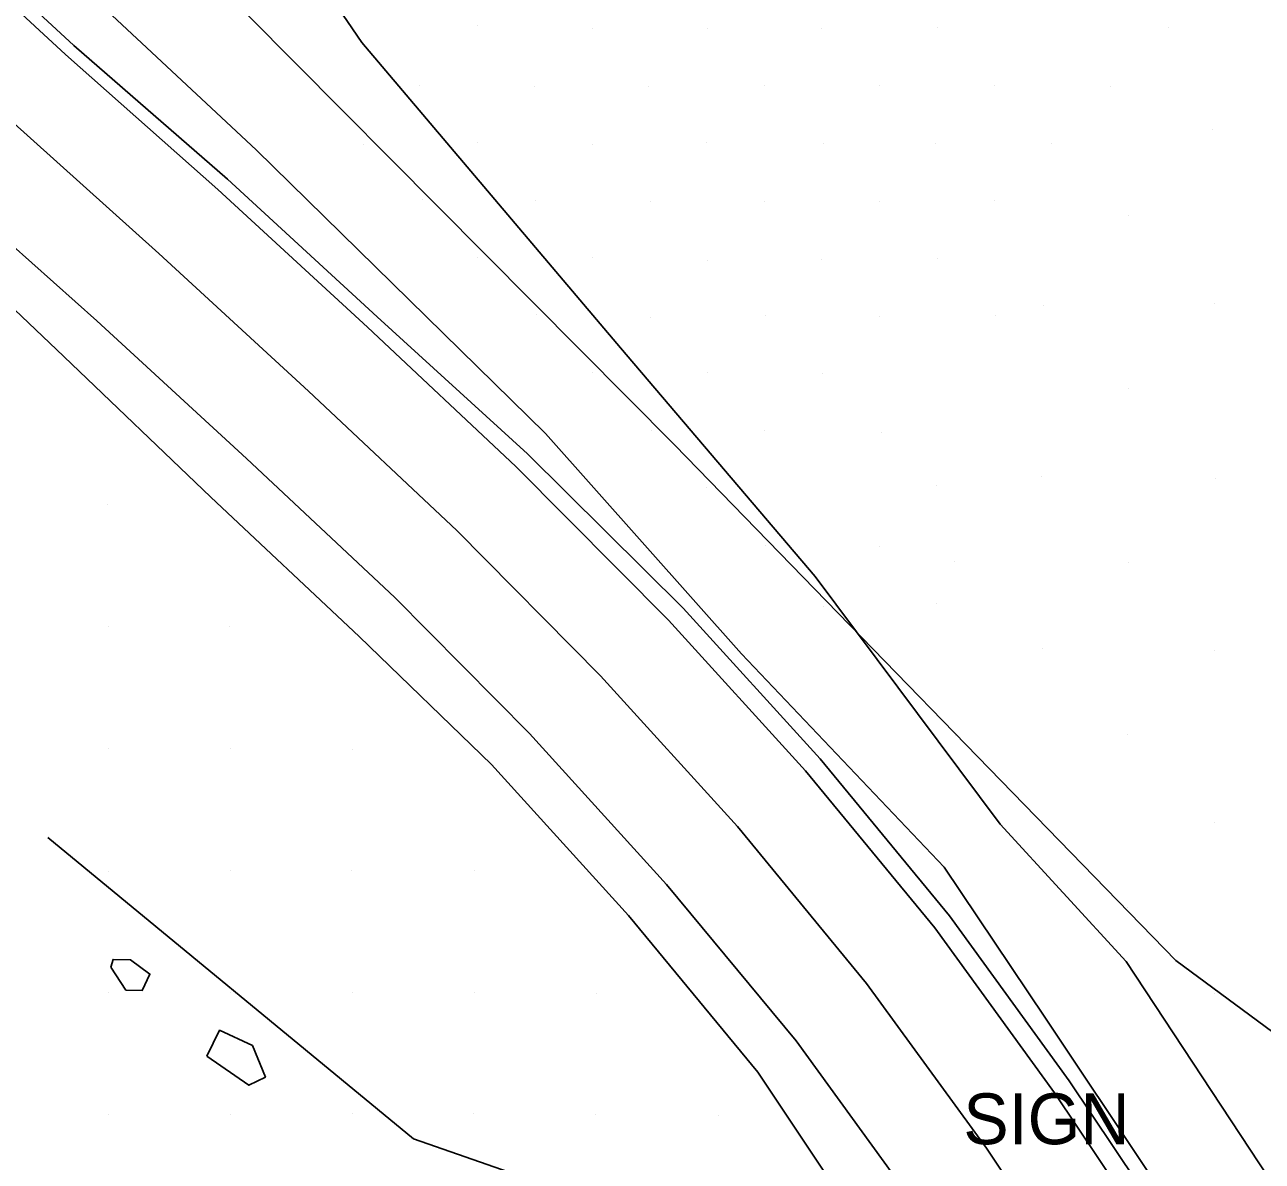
# Model space of a CAD drawing. Extents: x 1602514 to 1609837, y 863887 to 871157.
# Drawn here: x 1605243.4 to 1605395.4, y 866343.2 to 866482.9 of the extents above; entities that cross this region are included whole.
import ezdxf

# ---------------------------------------------------------------- set-up
doc = ezdxf.new("R2010")
doc.units = 0
for name, color, linetype in [('Roadway-Signs', 7, 'Continuous'), ('Survey-Centerline', 7, 'Continuous'), ('Survey-Edge of pavement', 7, 'Continuous'), ('Survey-Ridge Lines', 7, 'Continuous'), ('Survey-Shoulders', 7, 'Continuous'), ('Survey-Spot dirt', 7, 'Continuous'), ('Survey-Vegetation trees', 7, 'Continuous'), ('USER-Boulder', 7, 'Continuous')]:
    doc.layers.add(name, color=color, linetype=linetype)

msp = doc.modelspace()

# ---------------------------------------------------------------- linework, layer by layer
at = {"layer": 'Survey-Centerline'}
msp.add_lwpolyline([(1605037.69, 866656.39), (1605055.94, 866639.3), (1605074.48, 866622.54), (1605093.22, 866605.99), (1605111.81, 866589.27), (1605130.38, 866572.54), (1605149.03, 866555.9), (1605167.54, 866539.1), (1605186.09, 866522.35), (1605204.45, 866505.38), (1605222.87, 866488.48), (1605241.24, 866471.52), (1605259.83, 866454.8), (1605278.24, 866437.88), (1605296.47, 866420.77), (1605314.1, 866402.9), (1605330.94, 866384.38), (1605346.83, 866365.09), (1605361.55, 866344.83), (1605375.5, 866323.96)], dxfattribs=at)
msp.add_lwpolyline([(1605037.69, 866656.39), (1605055.94, 866639.3), (1605074.48, 866622.54), (1605093.22, 866605.99), (1605111.81, 866589.27), (1605130.38, 866572.54), (1605149.03, 866555.9), (1605167.54, 866539.1), (1605186.09, 866522.35), (1605204.45, 866505.38), (1605222.87, 866488.48), (1605241.24, 866471.52), (1605259.83, 866454.8), (1605278.24, 866437.88), (1605296.47, 866420.77), (1605314.1, 866402.9), (1605330.94, 866384.38), (1605346.83, 866365.09), (1605361.55, 866344.83), (1605375.5, 866323.96)], dxfattribs=at)
at = {"layer": 'Survey-Edge of pavement'}
for points in [[(1605045, 866665.21), (1605063.24, 866647.41), (1605081.79, 866630.65), (1605100.27, 866613.81), (1605118.67, 866596.89), (1605137.24, 866580.16), (1605155.84, 866563.45), (1605174.61, 866546.94), (1605193.13, 866529.98), (1605211.59, 866513.11), (1605230.01, 866496.21), (1605248.38, 866479.26), (1605267.08, 866462.66), (1605285.49, 866445.74), (1605303.72, 866428.63), (1605322.49, 866409.74), (1605339.33, 866391.21), (1605355.22, 866371.92), (1605369.93, 866351.67), (1605383.89, 866330.79)], [(1605045, 866665.21), (1605063.24, 866647.41), (1605081.79, 866630.65), (1605100.27, 866613.81), (1605118.67, 866596.89), (1605137.24, 866580.16), (1605155.84, 866563.45), (1605174.61, 866546.94), (1605193.13, 866529.98), (1605211.59, 866513.11), (1605230.01, 866496.21), (1605248.38, 866479.26), (1605267.08, 866462.66), (1605285.49, 866445.74), (1605303.72, 866428.63), (1605322.49, 866409.74), (1605339.33, 866391.21), (1605355.22, 866371.92), (1605369.93, 866351.67), (1605383.89, 866330.79)], [(1605024.15, 866652.85), (1605048.37, 866630.9), (1605067.06, 866614.3), (1605085.84, 866597.8), (1605104.37, 866581.02), (1605122.94, 866564.29), (1605141.59, 866547.64), (1605160.11, 866530.85), (1605178.38, 866513.98), (1605196.73, 866497.01), (1605215.15, 866480.11), (1605233.53, 866463.16), (1605252.21, 866446.54), (1605270.61, 866429.62), (1605288.84, 866412.51), (1605305.39, 866395.8), (1605322.22, 866377.27), (1605338.18, 866358.03), (1605352.89, 866337.77)], [(1605024.15, 866652.85), (1605048.37, 866630.9), (1605067.06, 866614.3), (1605085.84, 866597.8), (1605104.37, 866581.02), (1605122.94, 866564.29), (1605141.59, 866547.64), (1605160.11, 866530.85), (1605178.38, 866513.98), (1605196.73, 866497.01), (1605215.15, 866480.11), (1605233.53, 866463.16), (1605252.21, 866446.54), (1605270.61, 866429.62), (1605288.84, 866412.51), (1605305.39, 866395.8), (1605322.22, 866377.27), (1605338.18, 866358.03), (1605352.89, 866337.77)]]:
    msp.add_lwpolyline(points, dxfattribs=at)
at = {"layer": 'Survey-Ridge Lines'}
for points in [[(1605195.3, 866608.5), (1605255.31, 866523.97), (1605284.77, 866480.71), (1605316.58, 866443.2), (1605340.52, 866415.11), (1605363.23, 866384.67), (1605378.71, 866367.8), (1605403.27, 866330.55), (1605412.95, 866304.44), (1605430.55, 866268.66), (1605443.77, 866231.64), (1605454.66, 866201.21), (1605464.16, 866184.87), (1605467.92, 866182.17), (1605470.83, 866178.24), (1605475.29, 866169.59)], [(1605195.3, 866608.5), (1605255.31, 866523.97), (1605284.77, 866480.71), (1605316.58, 866443.2), (1605340.52, 866415.11), (1605363.23, 866384.67), (1605378.71, 866367.8), (1605403.27, 866330.55), (1605412.95, 866304.44), (1605430.55, 866268.66), (1605443.77, 866231.64), (1605454.66, 866201.21), (1605464.16, 866184.87), (1605467.92, 866182.17), (1605470.83, 866178.24), (1605475.29, 866169.59)], [(1605126.79, 866598.12), (1605151.68, 866575.67), (1605188.15, 866541.7), (1605235.1, 866501.78), (1605271.81, 866467.54), (1605307.34, 866432.68), (1605331.43, 866405.59), (1605356.35, 866379.4), (1605368.71, 866360.96), (1605381.73, 866341.47), (1605393.4, 866324.71), (1605405.98, 866300.67), (1605423.07, 866265.61), (1605436.8, 866229.87), (1605447.04, 866198.89), (1605457.58, 866178.46), (1605461.17, 866174.26), (1605463.72, 866171.59), (1605472.78, 866165.22)], [(1605126.79, 866598.12), (1605151.68, 866575.67), (1605188.15, 866541.7), (1605235.1, 866501.78), (1605271.81, 866467.54), (1605307.34, 866432.68), (1605331.43, 866405.59), (1605356.35, 866379.4), (1605368.71, 866360.96), (1605381.73, 866341.47), (1605393.4, 866324.71), (1605405.98, 866300.67), (1605423.07, 866265.61), (1605436.8, 866229.87), (1605447.04, 866198.89), (1605457.58, 866178.46), (1605461.17, 866174.26), (1605463.72, 866171.59), (1605472.78, 866165.22)]]:
    msp.add_lwpolyline(points, dxfattribs=at)
at = {"layer": 'Survey-Shoulders'}
for points in [[(1605020.8, 866649.24), (1605044.41, 866626.5), (1605062.62, 866609.38), (1605081.95, 866593.48), (1605100.89, 866577.16), (1605119.46, 866560.43), (1605138.12, 866543.79), (1605156.63, 866526.99), (1605174.63, 866509.92), (1605193.24, 866493.23), (1605211.66, 866476.33), (1605230.03, 866459.38), (1605248.15, 866442.14), (1605266.22, 866424.86), (1605284.45, 866407.75), (1605300.72, 866391.99), (1605317.55, 866373.46), (1605333.45, 866354.17), (1605347.38, 866333.28)], [(1605020.8, 866649.24), (1605044.41, 866626.5), (1605062.62, 866609.38), (1605081.95, 866593.48), (1605100.89, 866577.16), (1605119.46, 866560.43), (1605138.12, 866543.79), (1605156.63, 866526.99), (1605174.63, 866509.92), (1605193.24, 866493.23), (1605211.66, 866476.33), (1605230.03, 866459.38), (1605248.15, 866442.14), (1605266.22, 866424.86), (1605284.45, 866407.75), (1605300.72, 866391.99), (1605317.55, 866373.46), (1605333.45, 866354.17), (1605347.38, 866333.28)], [(1605118.67, 866596.89), (1605124.9, 866593.16), (1605138.16, 866581.18), (1605157.01, 866564.75), (1605175.69, 866548.14), (1605194.25, 866531.19), (1605212.61, 866514.22), (1605231.03, 866497.32), (1605249.4, 866480.36), (1605268.26, 866463.93), (1605286.67, 866447.02), (1605305.13, 866430.16), (1605324.29, 866411.21), (1605341.12, 866392.68), (1605357.02, 866373.39), (1605371.73, 866353.13), (1605385.69, 866332.26), (1605399.6, 866308.3), (1605412.28, 866286.71), (1605423.44, 866262.16), (1605432.42, 866238.83), (1605440.02, 866215.01), (1605447.78, 866189)], [(1605118.67, 866596.89), (1605124.9, 866593.16), (1605138.16, 866581.18), (1605157.01, 866564.75), (1605175.69, 866548.14), (1605194.25, 866531.19), (1605212.61, 866514.22), (1605231.03, 866497.32), (1605249.4, 866480.36), (1605268.26, 866463.93), (1605286.67, 866447.02), (1605305.13, 866430.16), (1605324.29, 866411.21), (1605341.12, 866392.68), (1605357.02, 866373.39), (1605371.73, 866353.13), (1605385.69, 866332.26), (1605399.6, 866308.3), (1605412.28, 866286.71), (1605423.44, 866262.16), (1605432.42, 866238.83), (1605440.02, 866215.01), (1605447.78, 866189)], [(1605246.18, 866383.04), (1605291.14, 866346), (1605319.22, 866336.19), (1605354.84, 866321.34)], [(1605246.18, 866383.04), (1605291.14, 866346), (1605319.22, 866336.19), (1605354.84, 866321.34)]]:
    msp.add_lwpolyline(points, dxfattribs=at)
at = {"layer": 'Survey-Spot dirt'}
for p, q in [((1605299.05, 866482.78), (1605299.05, 866482.78)), ((1605299.05, 866482.78), (1605299.05, 866482.78)), ((1605313.14, 866482.43), (1605313.14, 866482.43)), ((1605313.14, 866482.43), (1605313.14, 866482.43)), ((1605327.33, 866482.5), (1605327.33, 866482.5)), ((1605327.33, 866482.5), (1605327.33, 866482.5)), ((1605341.32, 866482.51), (1605341.32, 866482.51)), ((1605341.32, 866482.51), (1605341.32, 866482.51)), ((1605355.51, 866482.57), (1605355.51, 866482.57)), ((1605355.51, 866482.57), (1605355.51, 866482.57)), ((1605383.87, 866482.62), (1605383.87, 866482.62)), ((1605383.87, 866482.62), (1605383.87, 866482.62)), ((1605291.92, 866475.49), (1605291.92, 866475.49)), ((1605291.92, 866475.49), (1605291.92, 866475.49)), ((1605306.06, 866475.37), (1605306.06, 866475.37)), ((1605306.06, 866475.37), (1605306.06, 866475.37)), ((1605320.07, 866475.3), (1605320.07, 866475.3)), ((1605320.07, 866475.3), (1605320.07, 866475.3)), ((1605334.28, 866475.42), (1605334.28, 866475.42)), ((1605334.28, 866475.42), (1605334.28, 866475.42)), ((1605348.44, 866475.42), (1605348.44, 866475.42)), ((1605348.44, 866475.42), (1605348.44, 866475.42)), ((1605362.52, 866475.44), (1605362.52, 866475.44)), ((1605362.52, 866475.44), (1605362.52, 866475.44)), ((1605376.79, 866475.37), (1605376.79, 866475.37)), ((1605376.79, 866475.37), (1605376.79, 866475.37)), ((1605389.34, 866470.01), (1605389.34, 866470.01)), ((1605389.34, 866470.01), (1605389.34, 866470.01)), ((1605285, 866468.16), (1605285, 866468.16)), ((1605285, 866468.16), (1605285, 866468.16)), ((1605298.96, 866468.5), (1605298.96, 866468.5)), ((1605298.96, 866468.5), (1605298.96, 866468.5)), ((1605313.12, 866468.19), (1605313.12, 866468.19)), ((1605313.12, 866468.19), (1605313.12, 866468.19)), ((1605327.16, 866468.39), (1605327.16, 866468.39)), ((1605327.16, 866468.39), (1605327.16, 866468.39)), ((1605341.5, 866468.3), (1605341.5, 866468.3)), ((1605341.5, 866468.3), (1605341.5, 866468.3)), ((1605355.35, 866468.31), (1605355.35, 866468.31)), ((1605355.35, 866468.31), (1605355.35, 866468.31)), ((1605369.49, 866468.27), (1605369.49, 866468.27)), ((1605369.49, 866468.27), (1605369.49, 866468.27)), ((1605292.23, 866461.41), (1605292.23, 866461.41)), ((1605292.23, 866461.41), (1605292.23, 866461.41)), ((1605306.11, 866461.29), (1605306.11, 866461.29)), ((1605306.11, 866461.29), (1605306.11, 866461.29)), ((1605320.28, 866461.2), (1605320.28, 866461.2)), ((1605320.28, 866461.2), (1605320.28, 866461.2)), ((1605334.27, 866461.23), (1605334.27, 866461.23)), ((1605334.27, 866461.23), (1605334.27, 866461.23)), ((1605348.37, 866461.25), (1605348.37, 866461.25)), ((1605348.37, 866461.25), (1605348.37, 866461.25)), ((1605362.52, 866461.35), (1605362.52, 866461.35)), ((1605362.52, 866461.35), (1605362.52, 866461.35)), ((1605379.04, 866459.43), (1605379.04, 866459.43)), ((1605379.04, 866459.43), (1605379.04, 866459.43)), ((1605298.95, 866454.32), (1605298.95, 866454.32)), ((1605298.95, 866454.32), (1605298.95, 866454.32)), ((1605313.13, 866454.28), (1605313.13, 866454.28)), ((1605313.13, 866454.28), (1605313.13, 866454.28)), ((1605355.53, 866454.22), (1605355.53, 866454.22)), ((1605355.53, 866454.22), (1605355.53, 866454.22)), ((1605327.21, 866453.88), (1605327.21, 866453.88)), ((1605327.21, 866453.88), (1605327.21, 866453.88)), ((1605341.23, 866454.05), (1605341.23, 866454.05)), ((1605341.23, 866454.05), (1605341.23, 866454.05)), ((1605368.56, 866448.38), (1605368.56, 866448.38)), ((1605368.56, 866448.38), (1605368.56, 866448.38)), ((1605389.55, 866448.65), (1605389.55, 866448.65)), ((1605389.55, 866448.65), (1605389.55, 866448.65)), ((1605306.23, 866447.28), (1605306.23, 866447.28)), ((1605306.23, 866447.28), (1605306.23, 866447.28)), ((1605320.22, 866446.96), (1605320.22, 866446.96)), ((1605320.22, 866446.96), (1605320.22, 866446.96)), ((1605334.34, 866447.18), (1605334.34, 866447.18)), ((1605334.34, 866447.18), (1605334.34, 866447.18)), ((1605348.38, 866447.04), (1605348.38, 866447.04)), ((1605348.38, 866447.04), (1605348.38, 866447.04)), ((1605362.64, 866447.16), (1605362.64, 866447.16)), ((1605362.64, 866447.16), (1605362.64, 866447.16)), ((1605313.15, 866440.13), (1605313.15, 866440.13)), ((1605313.15, 866440.13), (1605313.15, 866440.13)), ((1605327.21, 866440.12), (1605327.21, 866440.12)), ((1605327.21, 866440.12), (1605327.21, 866440.12)), ((1605341.35, 866440.04), (1605341.35, 866440.04)), ((1605341.35, 866440.04), (1605341.35, 866440.04)), ((1605378.95, 866438.19), (1605378.95, 866438.19)), ((1605378.95, 866438.19), (1605378.95, 866438.19)), ((1605320.33, 866433.06), (1605320.33, 866433.06)), ((1605320.33, 866433.06), (1605320.33, 866433.06)), ((1605334.32, 866433.07), (1605334.32, 866433.07)), ((1605334.32, 866433.07), (1605334.32, 866433.07)), ((1605348.64, 866432.84), (1605348.64, 866432.84)), ((1605348.64, 866432.84), (1605348.64, 866432.84)), ((1605368.29, 866427.42), (1605368.29, 866427.42)), ((1605368.29, 866427.42), (1605368.29, 866427.42)), ((1605389.7, 866427.15), (1605389.7, 866427.15)), ((1605389.7, 866427.15), (1605389.7, 866427.15)), ((1605327.2, 866426.03), (1605327.2, 866426.03)), ((1605327.2, 866426.03), (1605327.2, 866426.03)), ((1605355.41, 866426.25), (1605355.41, 866426.25)), ((1605355.41, 866426.25), (1605355.41, 866426.25)), ((1605253.59, 866424), (1605253.59, 866424)), ((1605253.59, 866424), (1605253.59, 866424)), ((1605334.34, 866418.86), (1605334.34, 866418.86)), ((1605334.34, 866418.86), (1605334.34, 866418.86)), ((1605348.41, 866418.81), (1605348.41, 866418.81)), ((1605348.41, 866418.81), (1605348.41, 866418.81)), ((1605357.66, 866416.92), (1605357.66, 866416.92)), ((1605357.66, 866416.92), (1605357.66, 866416.92)), ((1605379.01, 866416.87), (1605379.01, 866416.87)), ((1605379.01, 866416.87), (1605379.01, 866416.87)), ((1605355.4, 866411.8), (1605355.4, 866411.8)), ((1605355.4, 866411.8), (1605355.4, 866411.8)), ((1605341.56, 866411.46), (1605341.56, 866411.46)), ((1605341.56, 866411.46), (1605341.56, 866411.46)), ((1605253.61, 866409.02), (1605253.61, 866409.02)), ((1605253.61, 866409.02), (1605253.61, 866409.02)), ((1605268.58, 866408.98), (1605268.58, 866408.98)), ((1605268.58, 866408.98), (1605268.58, 866408.98)), ((1605347.18, 866406.25), (1605347.18, 866406.25)), ((1605347.18, 866406.25), (1605347.18, 866406.25)), ((1605368.4, 866406.27), (1605368.4, 866406.27)), ((1605368.4, 866406.27), (1605368.4, 866406.27)), ((1605389.64, 866406.07), (1605389.64, 866406.07)), ((1605389.64, 866406.07), (1605389.64, 866406.07)), ((1605357.77, 866395.62), (1605357.77, 866395.62)), ((1605357.77, 866395.62), (1605357.77, 866395.62)), ((1605378.84, 866395.73), (1605378.84, 866395.73)), ((1605378.84, 866395.73), (1605378.84, 866395.73)), ((1605253.63, 866393.95), (1605253.63, 866393.95)), ((1605253.63, 866393.95), (1605253.63, 866393.95)), ((1605268.59, 866393.99), (1605268.59, 866393.99)), ((1605268.59, 866393.99), (1605268.59, 866393.99)), ((1605283.63, 866393.89), (1605283.63, 866393.89)), ((1605283.63, 866393.89), (1605283.63, 866393.89)), ((1605368.43, 866385.09), (1605368.43, 866385.09)), ((1605368.43, 866385.09), (1605368.43, 866385.09)), ((1605389.64, 866384.82), (1605389.64, 866384.82)), ((1605389.64, 866384.82), (1605389.64, 866384.82)), ((1605253.66, 866378.91), (1605253.66, 866378.91)), ((1605253.66, 866378.91), (1605253.66, 866378.91)), ((1605268.62, 866378.93), (1605268.62, 866378.93)), ((1605268.62, 866378.93), (1605268.62, 866378.93)), ((1605283.56, 866379.02), (1605283.56, 866379.02)), ((1605283.56, 866379.02), (1605283.56, 866379.02)), ((1605298.63, 866378.98), (1605298.63, 866378.98)), ((1605298.63, 866378.98), (1605298.63, 866378.98)), ((1605378.88, 866374.39), (1605378.88, 866374.39)), ((1605378.88, 866374.39), (1605378.88, 866374.39)), ((1605253.67, 866363.98), (1605253.67, 866363.98)), ((1605253.67, 866363.98), (1605253.67, 866363.98)), ((1605268.66, 866363.97), (1605268.66, 866363.97)), ((1605268.66, 866363.97), (1605268.66, 866363.97)), ((1605283.65, 866363.92), (1605283.65, 866363.92)), ((1605283.65, 866363.92), (1605283.65, 866363.92)), ((1605298.68, 866364.02), (1605298.68, 866364.02)), ((1605298.68, 866364.02), (1605298.68, 866364.02)), ((1605313.66, 866363.91), (1605313.66, 866363.91)), ((1605313.66, 866363.91), (1605313.66, 866363.91)), ((1605389.52, 866363.84), (1605389.52, 866363.84)), ((1605389.52, 866363.84), (1605389.52, 866363.84)), ((1605253.63, 866348.99), (1605253.63, 866348.99)), ((1605253.63, 866348.99), (1605253.63, 866348.99)), ((1605268.61, 866348.94), (1605268.61, 866348.94)), ((1605268.61, 866348.94), (1605268.61, 866348.94)), ((1605283.58, 866349.07), (1605283.58, 866349.07)), ((1605283.58, 866349.07), (1605283.58, 866349.07)), ((1605298.53, 866349.05), (1605298.53, 866349.05)), ((1605298.53, 866349.05), (1605298.53, 866349.05)), ((1605313.55, 866349), (1605313.55, 866349)), ((1605313.55, 866349), (1605313.55, 866349)), ((1605328.65, 866348.92), (1605328.65, 866348.92)), ((1605328.65, 866348.92), (1605328.65, 866348.92))]:
    msp.add_line(p, q, dxfattribs=at)
at = {"layer": 'Survey-Vegetation trees'}
msp.add_lwpolyline([(1605601.79, 866275.83), (1605605.2, 866448.65), (1605612.42, 866530.39), (1605609.93, 866556.1), (1605459.73, 866746.47), (1605424.26, 866753.41), (1605387.87, 866745.45), (1605328.37, 866764.72), (1605298.66, 866722.79), (1605306.28, 866699.16), (1605277.32, 866658.75), (1605265.13, 866625.97), (1605217.79, 866602.88), (1605158.36, 866628.8), (1605148.45, 866592.97), (1605247.5, 866507.58), (1605323.27, 866431.24), (1605384.81, 866367.9), (1605438.61, 866328.19), (1605473.87, 866349.1), (1605499.88, 866323.66)], dxfattribs=at)
msp.add_lwpolyline([(1605601.79, 866275.83), (1605605.2, 866448.65), (1605612.42, 866530.39), (1605609.93, 866556.1), (1605459.73, 866746.47), (1605424.26, 866753.41), (1605387.87, 866745.45), (1605328.37, 866764.72), (1605298.66, 866722.79), (1605306.28, 866699.16), (1605277.32, 866658.75), (1605265.13, 866625.97), (1605217.79, 866602.88), (1605158.36, 866628.8), (1605148.45, 866592.97), (1605247.5, 866507.58), (1605323.27, 866431.24), (1605384.81, 866367.9), (1605438.61, 866328.19), (1605473.87, 866349.1), (1605499.88, 866323.66)], dxfattribs=at)
at = {"layer": 'USER-Boulder'}
for points in [[(1605253.95, 866367.09), (1605255.8, 866364.28), (1605257.81, 866364.23), (1605258.75, 866366.25), (1605256.35, 866367.98), (1605254.21, 866368.05), (1605253.95, 866367.09)], [(1605253.95, 866367.09), (1605255.8, 866364.28), (1605257.81, 866364.23), (1605258.75, 866366.25), (1605256.35, 866367.98), (1605254.21, 866368.05), (1605253.95, 866367.09)], [(1605265.74, 866356.15), (1605270.91, 866352.58), (1605272.93, 866353.59), (1605271.34, 866357.46), (1605267.3, 866359.35), (1605265.74, 866356.15)], [(1605265.74, 866356.15), (1605270.91, 866352.58), (1605272.93, 866353.59), (1605271.34, 866357.46), (1605267.3, 866359.35), (1605265.74, 866356.15)]]:
    msp.add_lwpolyline(points, dxfattribs=at)

# ---------------------------------------------------------------- texts
at = {"layer": 'Roadway-Signs'}
msp.add_text('SIGN', height=6.25, dxfattribs=at).set_placement((1605358.71, 866345.33))
msp.add_text('SIGN', height=6.25, dxfattribs=at).set_placement((1605358.71, 866345.33))

doc.saveas('drawing.dxf')
